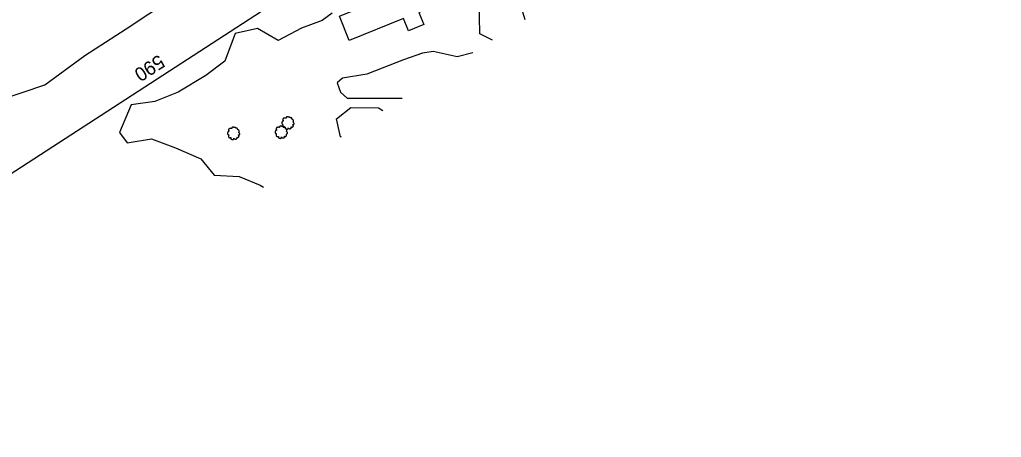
# Model space of a CAD drawing. Extents: x 1901471 to 1963503, y 756461 to 799997.
# Drawn here: x 1922598 to 1923167, y 768431 to 768672 of the extents above; entities that cross this region are included whole.
import ezdxf

# ---------------------------------------------------------------- set-up
doc = ezdxf.new("R2010")
doc.units = 0
for name, color, linetype in [('RD_EX_Bldg', 7, 'Continuous'), ('RD_EX_Driveway', 7, 'Continuous'), ('RD_EX_Fence_Other', 7, 'Continuous'), ('RD_EX_VEG', 7, 'Continuous'), ('RD_HC_TX_Sta50', 7, 'Continuous')]:
    doc.layers.add(name, color=color, linetype=linetype)

# ---------------------------------------------------------------- blocks, each defined once
blk = doc.blocks.new('T2')
at = {"layer": 'RD_EX_VEG'}
for points in [[(0.05233333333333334, 7.213166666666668), (-0.24750000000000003, 7.238166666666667), (-0.5723333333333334, 7.138166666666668), (-0.8222500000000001, 7.038250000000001), (-1.0471666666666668, 6.963250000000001), (-1.2720833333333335, 6.863250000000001), (-1.5719166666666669, 6.688416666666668), (-1.7968333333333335, 6.488416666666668), (-1.9218333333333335, 6.2385833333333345), (-1.9718333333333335, 6.013666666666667), (-2.0217500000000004, 5.738833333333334), (-2.0217500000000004, 5.563833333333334), (-2.146666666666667, 5.538833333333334), (-2.296666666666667, 5.563833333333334), (-2.5465000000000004, 5.638833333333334), (-2.796416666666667, 5.638833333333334), (-3.0463333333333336, 5.638833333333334), (-3.3961666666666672, 5.613833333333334), (-3.7460000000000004, 5.613833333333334), (-4.020833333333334, 5.563833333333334), (-4.345750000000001, 5.513916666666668), (-4.720583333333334, 5.389000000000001), (-5.0704166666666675, 5.264000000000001), (-5.37025, 5.014083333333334), (-5.620166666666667, 4.539333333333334), (-5.745166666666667, 4.189500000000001), (-5.895083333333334, 3.9395833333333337), (-5.745166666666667, 3.489833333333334), (-5.570166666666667, 3.139916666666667), (-5.545250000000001, 2.9400000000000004), (-5.470250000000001, 2.5152500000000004), (-5.37025, 2.2903333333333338), (-5.245333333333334, 2.0903333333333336), (-5.320250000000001, 2.065416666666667), (-5.695166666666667, 2.015416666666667), (-5.995000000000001, 1.9155000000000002), (-6.419833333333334, 1.6905833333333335), (-6.644750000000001, 1.465666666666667), (-6.744750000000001, 1.1407500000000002), (-6.769666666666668, 0.7909166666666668), (-6.869583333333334, 0.5910833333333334), (-6.944583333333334, 0.3161666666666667), (-6.969583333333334, 0.2411666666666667), (-7.019583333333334, -0.08366666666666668), (-6.9195833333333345, -0.5335000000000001), (-6.894583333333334, -0.8833333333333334), (-6.769666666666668, -1.1082500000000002), (-6.619750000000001, -1.2830833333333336), (-6.444833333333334, -1.5330000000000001), (-6.045000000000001, -1.7579166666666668), (-5.7201666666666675, -1.8579166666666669), (-5.520250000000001, -1.8828333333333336), (-5.695166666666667, -2.382666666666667), (-5.745166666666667, -2.7325000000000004), (-5.870083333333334, -3.132333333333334), (-5.870083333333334, -3.2072500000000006), (-5.920000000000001, -3.682083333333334), (-5.770166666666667, -4.007000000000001), (-5.695166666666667, -4.38175), (-5.520250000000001, -4.606666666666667), (-5.245333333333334, -4.906583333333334), (-4.9205000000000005, -5.131416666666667), (-4.420666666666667, -5.256416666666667), (-4.020833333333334, -5.231416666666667), (-3.4460833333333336, -5.056500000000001), (-3.1962500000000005, -4.9815000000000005), (-3.2212500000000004, -5.156416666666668), (-3.1962500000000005, -5.531333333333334), (-3.1962500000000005, -5.956083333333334), (-3.0463333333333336, -6.280916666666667), (-2.946333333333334, -6.555833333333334), (-2.796416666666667, -6.805750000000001), (-2.4715000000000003, -7.030583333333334), (-2.07175, -7.1055833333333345), (-1.6469166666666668, -7.2555000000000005), (-1.1970833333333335, -7.330500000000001), (-0.6973333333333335, -7.355500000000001), (-0.09758333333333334, -7.205583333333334), (0.17725000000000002, -7.080583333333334), (0.27725000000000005, -6.905666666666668), (0.47716666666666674, -6.530833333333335), (0.4271666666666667, -6.3059166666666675), (0.4521666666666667, -5.706166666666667), (0.5520833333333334, -5.881166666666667), (0.7270833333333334, -6.231000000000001), (1.2268333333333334, -6.530833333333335), (1.626666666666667, -6.705750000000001), (2.101416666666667, -6.8557500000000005), (2.4013333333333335, -6.930666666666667), (2.8760833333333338, -6.8557500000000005), (3.2510000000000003, -6.780750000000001), (3.6257500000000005, -6.655750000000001), (3.9256666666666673, -6.380916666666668), (4.100583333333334, -6.106000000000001), (4.1505833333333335, -5.831166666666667), (4.2255, -5.456333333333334), (4.275500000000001, -5.281416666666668)], [(4.275500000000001, -5.281416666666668), (4.200583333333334, -5.106416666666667), (4.1505833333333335, -4.856583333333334), (4.2255, -4.881583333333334), (4.4004166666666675, -4.931583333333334), (4.675333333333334, -5.056500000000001), (4.900250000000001, -5.131416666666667), (5.225083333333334, -5.106416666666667), (5.500000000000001, -5.006500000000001), (5.949750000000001, -4.731583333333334), (6.224666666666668, -4.256833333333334), (6.499500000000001, -3.8570000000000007), (6.5745000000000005, -3.5321666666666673), (6.524500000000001, -3.3072500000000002), (6.499500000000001, -2.8075000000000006), (6.299583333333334, -2.5575833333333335), (6.249583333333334, -2.432666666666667), (6.1496666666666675, -2.0328333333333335), (6.224666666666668, -1.9828333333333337), (6.499500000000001, -1.9328333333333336), (6.874333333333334, -1.8079166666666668), (7.149250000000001, -1.6830000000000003), (7.374166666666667, -1.5080000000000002), (7.449083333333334, -1.2830833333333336), (7.424166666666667, -0.8833333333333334), (7.4740833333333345, -0.48350000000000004), (7.399166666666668, -0.3335), (7.299166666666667, -0.1836666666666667), (7.224166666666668, 0.016333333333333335), (7.074250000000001, 0.16616666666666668), (6.974333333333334, 0.3161666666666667), (6.874333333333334, 0.41608333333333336), (6.749416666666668, 0.5660833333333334), (6.5745000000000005, 0.6910000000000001), (6.424583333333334, 0.7410000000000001), (6.374583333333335, 0.8909166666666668), (6.524500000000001, 1.0908333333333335), (6.5745000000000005, 1.1907500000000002), (6.599416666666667, 1.4156666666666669), (6.824416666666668, 1.7655000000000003), (6.874333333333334, 2.1653333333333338), (6.824416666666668, 2.590166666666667), (6.774416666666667, 2.8650833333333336), (6.624416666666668, 3.139916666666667), (6.424583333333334, 3.3898333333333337), (6.299583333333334, 3.5647500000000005), (6.124666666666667, 3.689666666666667), (5.799833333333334, 3.814666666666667), (5.549916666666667, 3.864583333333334), (5.200083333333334, 3.864583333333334), (5.000166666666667, 3.9145833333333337), (5.025166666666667, 3.964583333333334), (5.025166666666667, 4.1145000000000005), (5.025166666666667, 4.389416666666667), (4.950166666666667, 4.839166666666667), (4.800250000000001, 5.339), (4.800250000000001, 5.364000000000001), (4.7002500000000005, 5.613833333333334), (4.475416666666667, 5.813750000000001), (4.3005, 5.913666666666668), (4.100583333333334, 6.038666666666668), (3.850666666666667, 6.063666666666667), (3.5508333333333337, 6.063666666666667), (3.2759166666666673, 6.013666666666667), (3.0760000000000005, 5.913666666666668), (2.9010833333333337, 5.788750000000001), (2.8260833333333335, 5.938666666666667), (2.726166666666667, 6.2385833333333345), (2.676166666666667, 6.3885000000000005), (2.52625, 6.563416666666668), (2.301416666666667, 6.7633333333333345), (1.8515000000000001, 6.888250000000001), (1.2268333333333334, 6.813333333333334), (0.9269166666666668, 6.613416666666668), (0.7770000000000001, 6.438500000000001), (0.7270833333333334, 6.563416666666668), (0.5270833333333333, 6.7633333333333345), (0.4271666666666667, 6.938250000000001), (0.25225000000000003, 7.063250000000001), (0.10233333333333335, 7.163166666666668), (0.0023333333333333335, 7.213166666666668)]]:
    blk.add_spline(points, degree=3, dxfattribs=at)

msp = doc.modelspace()

# ---------------------------------------------------------------- linework, layer by layer
at = {"layer": 'RD_EX_Bldg'}
msp.add_lwpolyline([(1922783.7400000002, 768674.2500000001), (1922846.8100000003, 768699.6700000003), (1922852.4400000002, 768685.7000000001), (1922829.6200000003, 768676.5000000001), (1922832.4700000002, 768669.4300000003), (1922823.64, 768665.8700000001), (1922820.7700000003, 768672.9800000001), (1922789.3600000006, 768660.32)], close=True, dxfattribs=at)
at = {"layer": 'RD_EX_Driveway'}
msp.add_lwpolyline([(1922860.8400000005, 768653.05), (1922851.7700000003, 768650.7700000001), (1922837.8400000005, 768653.9100000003), (1922831.7200000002, 768652.9800000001), (1922820.6500000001, 768649.1000000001), (1922799.4500000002, 768640.83), (1922785.4300000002, 768638.5000000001), (1922782.2800000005, 768635.7600000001), (1922784.2200000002, 768630.2800000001), (1922788.0600000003, 768626.9900000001), (1922805.7400000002, 768626.9300000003), (1922819.9200000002, 768626.8400000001)], dxfattribs=at)
at = {"layer": 'RD_EX_Fence_Other'}
msp.add_lwpolyline([(1921110.7900000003, 767601.3900000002), (1921109.2600000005, 767622.0400000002), (1921196.1600000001, 767680.9100000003), (1921463.6600000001, 767858.3900000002), (1921595.6900000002, 767940.9200000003), (1921869.64, 768116.8), (1922122.4000000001, 768277.1500000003), (1922266.8400000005, 768373.7900000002), (1922394.4100000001, 768454.7500000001), (1922507.1200000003, 768527.4200000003), (1922756.1000000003, 768688.7700000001), (1922880.0600000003, 768768.9000000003), (1922970.5000000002, 768828.4600000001), (1923064.3800000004, 768888.4800000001), (1923170.7600000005, 768956.3500000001)], dxfattribs=at)
at = {"layer": 'RD_EX_VEG'}
for points in [[(1922872.2700000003, 768660.3800000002), (1922864.8700000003, 768664.07), (1922864.5000000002, 768684.3800000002), (1922864.4800000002, 768702.1800000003), (1922867.4600000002, 768707.4500000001), (1922875.4500000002, 768706.81), (1922884.5300000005, 768694.2700000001), (1922891.0200000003, 768672.3800000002)], [(1922587.4600000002, 768625.9500000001), (1922613.0200000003, 768634.57), (1922636.2300000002, 768651.4900000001), (1922660.1900000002, 768666.9500000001), (1922686.4100000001, 768684.4900000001)], [(1922779.4300000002, 768676.1400000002), (1922773.64, 768671.7200000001), (1922761.64, 768667.3900000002), (1922748.1000000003, 768660.2400000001), (1922736.2000000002, 768667.2300000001), (1922723.3100000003, 768664.2800000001), (1922717.3600000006, 768648.2200000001), (1922706.3500000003, 768640.08), (1922690.3000000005, 768630.3700000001), (1922676.8200000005, 768624.8900000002), (1922663.0400000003, 768623.0400000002), (1922656.3400000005, 768607.1100000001), (1922660.7600000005, 768601.0400000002), (1922674.8000000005, 768603.4600000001), (1922688.7900000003, 768598.2500000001), (1922703.3500000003, 768591.7200000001), (1922711.0900000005, 768582.3400000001), (1922725.6600000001, 768581.58), (1922737.8300000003, 768576.5200000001), (1922739.6800000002, 768575.4500000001)], [(1922784.8200000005, 768604.3600000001), (1922784.3400000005, 768604.56), (1922781.9300000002, 768614.9500000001), (1922790.1600000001, 768621.5900000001), (1922806.2000000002, 768621.2600000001), (1922808.8600000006, 768619.7600000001)]]:
    msp.add_lwpolyline(points, dxfattribs=at)

# ---------------------------------------------------------------- block references
at = {"layer": 'RD_EX_VEG', "xscale": 0.4921259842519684, "yscale": 0.4921259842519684}
for p in [(1922753.7200000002, 768612.6200000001), (1922722.2500000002, 768606.6200000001), (1922749.8500000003, 768607.2700000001)]:
    msp.add_blockref('T2', p, dxfattribs=at)

# ---------------------------------------------------------------- texts
at = {"layer": 'RD_HC_TX_Sta50'}
msp.add_text('590', height=8.000000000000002, rotation=212.85416067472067, dxfattribs=at).set_placement((1922679.0650534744, 768652.3920662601))

doc.saveas('drawing.dxf')
